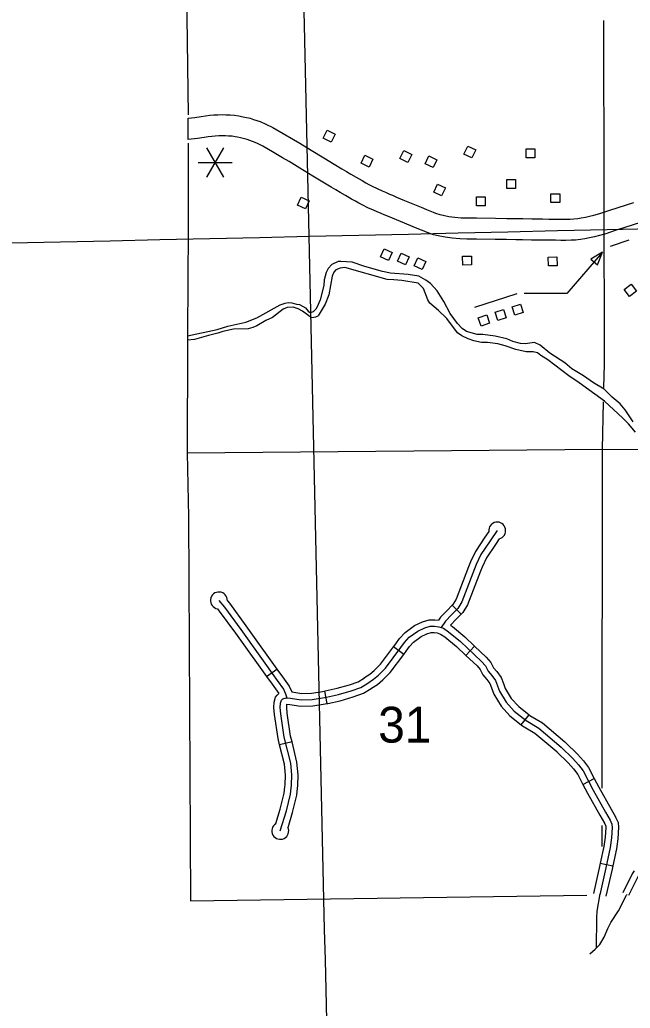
# Model space of a CAD drawing. Extents: x -19 to 366, y -4 to 359.
# Drawn here: x 127.169 to 128.531, y 197.843 to 200.051 of the extents above; entities that cross this region are included whole.
import ezdxf

# ---------------------------------------------------------------- set-up
doc = ezdxf.new("R2010")
doc.units = 0
for name, color, linetype in [('21', 7, 'Continuous'), ('R_Alt Surface', 7, 'Continuous'), ('R_Axis Annot', 7, 'Continuous'), ('R_Contour Annot', 7, 'Continuous'), ('R_ROW Annot', 7, 'Continuous'), ('R_Temp Easement', 7, 'Continuous'), ('Sheet Fence', 7, 'Continuous'), ('T_Indications', 7, 'Continuous'), ('T_Vehicle Path Lt Minor', 7, 'Continuous')]:
    doc.layers.add(name, color=color, linetype=linetype)

msp = doc.modelspace()

# ---------------------------------------------------------------- linework, layer by layer
at = {"layer": '21'}
for points in [[(127.8462, 199.7864), (127.8547, 199.8042), (127.8725, 199.7956), (127.864, 199.7779)], [(128.0174, 199.741), (128.026, 199.7588), (128.0438, 199.7502), (128.0352, 199.7325)], [(128.1602, 199.7511), (128.1687, 199.7689), (128.1865, 199.7603), (128.178, 199.7426)], [(128.2989, 199.7429), (128.2989, 199.7626), (128.3186, 199.7626), (128.3186, 199.7429)], [(127.9308, 199.7307), (127.9393, 199.7485), (127.9571, 199.7399), (127.9486, 199.7222)], [(128.0736, 199.7294), (128.0821, 199.7472), (128.0999, 199.7386), (128.0914, 199.7209)], [(128.2556, 199.6742), (128.2556, 199.694), (128.2753, 199.694), (128.2753, 199.6742)], [(128.0927, 199.6662), (128.1012, 199.6839), (128.1191, 199.6754), (128.1105, 199.6576)], [(128.3544, 199.6429), (128.3544, 199.6626), (128.3742, 199.6626), (128.3742, 199.6429)], [(127.7887, 199.6373), (127.797, 199.6552), (127.8149, 199.6469), (127.8066, 199.629)], [(128.1881, 199.6358), (128.1881, 199.6555), (128.2079, 199.6555), (128.2079, 199.6358)], [(127.9919, 199.5134), (127.974, 199.5216), (127.9822, 199.5396), (128.0001, 199.5314)], [(128.0301, 199.5038), (128.0122, 199.512), (128.0204, 199.53), (128.0383, 199.5218)], [(128.4436, 199.5167), (128.4582, 199.5041), (128.4698, 199.5324)], [(128.0671, 199.493), (128.0491, 199.5012), (128.0573, 199.5191), (128.0753, 199.511)], [(128.1773, 199.5034), (128.1576, 199.503), (128.1572, 199.5228), (128.177, 199.5231)], [(128.3683, 199.5018), (128.3486, 199.5014), (128.3482, 199.5212), (128.3679, 199.5216)], [(128.5456, 199.4446), (128.5297, 199.4329), (128.518, 199.4488), (128.5338, 199.4605)], [(128.2358, 199.3791), (128.2298, 199.3979), (128.2487, 199.4039), (128.2546, 199.3851)], [(128.2735, 199.3911), (128.2675, 199.4099), (128.2863, 199.4159), (128.2923, 199.3971)], [(128.2174, 199.3732), (128.1987, 199.3668), (128.1923, 199.3855), (128.211, 199.3919)]]:
    msp.add_lwpolyline(points, close=True, dxfattribs=at)
for points in [[(128.4872, 199.5457), (128.5293, 199.5594)], [(128.4698, 199.5324), (128.3901, 199.4397), (128.2946, 199.4397)], [(128.1847, 199.4091), (128.2787, 199.4395)]]:
    msp.add_lwpolyline(points, dxfattribs=at)
at = {"layer": 'R_Alt Surface'}
for points in [[(127.5449, 200.3115), (127.5416, 200.0569), (127.5444, 199.839)], [(127.5448, 199.7755), (127.5444, 199.5835), (127.5434, 199.3511), (127.5433, 199.3288), (127.5422, 199.084), (127.5454, 198.9405), (127.5498, 198.0835)], [(127.5498, 198.0835), (128.4346, 198.0961)]]:
    msp.add_lwpolyline(points, dxfattribs=at)
at = {"layer": 'R_Axis Annot'}
for points in [[(128.4726, 199.2294), (128.4738, 199.2814), (128.4724, 200.0492)], [(128.4695, 199.0922), (128.4719, 199.1976)], [(127.5422, 199.084), (128.4695, 199.0922)], [(128.4688, 198.3346), (128.4695, 199.0922)], [(128.4695, 199.0922), (128.5738, 199.0915)], [(128.4687, 198.2045), (128.4687, 198.2515)]]:
    msp.add_lwpolyline(points, dxfattribs=at)
at = {"layer": 'R_Contour Annot'}
for points in [[(127.5448, 199.7835), (127.5445, 199.8313), (127.5594, 199.8332), (127.5738, 199.8351), (127.5835, 199.8365), (127.5928, 199.8377), (127.6018, 199.8385), (127.6108, 199.839), (127.6203, 199.8393), (127.6291, 199.8391), (127.6383, 199.8388), (127.6482, 199.8378), (127.6576, 199.8365), (127.6639, 199.8352), (127.6711, 199.8339), (127.6828, 199.8311), (127.6907, 199.8287), (127.7055, 199.8236), (127.718, 199.8182), (127.7333, 199.8107), (127.7568, 199.7971), (127.7795, 199.7835), (127.794, 199.7752), (127.819, 199.7599), (127.8477, 199.7424), (127.8702, 199.7287), (127.888, 199.718), (127.8979, 199.712), (127.9077, 199.7065), (127.9195, 199.6996), (127.9328, 199.6918), (127.9414, 199.687), (127.9483, 199.6833), (127.9556, 199.6794), (127.9664, 199.6742), (127.9778, 199.6688), (127.9849, 199.6658), (127.9943, 199.6618), (128.0009, 199.659), (128.0099, 199.6551), (128.0278, 199.6477), (128.0459, 199.6402), (128.0649, 199.6322), (128.077, 199.6272), (128.0881, 199.6229), (128.0918, 199.6215), (128.097, 199.6194), (128.1061, 199.6164), (128.1135, 199.6145), (128.1265, 199.6119), (128.1396, 199.6101), (128.1537, 199.6089), (128.1676, 199.6085), (128.1884, 199.6084), (128.2308, 199.6077), (128.256, 199.6073), (128.2766, 199.607), (128.2917, 199.6069), (128.3117, 199.6065), (128.3253, 199.6064), (128.3355, 199.6062), (128.3494, 199.6059), (128.3651, 199.6058), (128.3764, 199.6057), (128.3869, 199.6057), (128.3976, 199.606), (128.4052, 199.6063), (128.4143, 199.6074), (128.4222, 199.6085), (128.4312, 199.6102), (128.4402, 199.6121), (128.4502, 199.6148), (128.4633, 199.6186), (128.4835, 199.6251), (128.5046, 199.6319), (128.5393, 199.6433)], [(128.554, 199.5982), (128.5192, 199.5869), (128.4981, 199.5801), (128.4771, 199.5733), (128.4629, 199.5692), (128.4514, 199.5661), (128.4405, 199.5638), (128.4299, 199.5618), (128.4205, 199.5604), (128.409, 199.5591), (128.3992, 199.5587), (128.3875, 199.5584), (128.3762, 199.5584), (128.3647, 199.5585), (128.3487, 199.5586), (128.3346, 199.5589), (128.3248, 199.559), (128.3111, 199.5591), (128.2911, 199.5595), (128.2761, 199.5597), (128.2552, 199.56), (128.2301, 199.5604), (128.1879, 199.561), (128.1669, 199.5612), (128.1511, 199.5616), (128.1343, 199.563), (128.1185, 199.5652), (128.103, 199.5683), (128.0926, 199.5709), (128.0807, 199.575), (128.0744, 199.5775), (128.0711, 199.5788), (128.0595, 199.5832), (128.0467, 199.5885), (128.0276, 199.5965), (128.0096, 199.604), (127.9915, 199.6115), (127.9824, 199.6154), (127.9758, 199.6182), (127.9662, 199.6223), (127.9584, 199.6256), (127.946, 199.6314), (127.9343, 199.6372), (127.9259, 199.6415), (127.9185, 199.6456), (127.9093, 199.6507), (127.8957, 199.6587), (127.8842, 199.6654), (127.8741, 199.6711), (127.8635, 199.6775), (127.8456, 199.6882), (127.8231, 199.7019), (127.7943, 199.7195), (127.7698, 199.7344), (127.7555, 199.7427), (127.7328, 199.7563), (127.711, 199.7689), (127.6982, 199.7752), (127.6883, 199.7794), (127.6761, 199.7837), (127.6704, 199.7854), (127.6612, 199.7876), (127.6551, 199.7887), (127.6498, 199.7897), (127.6426, 199.7908), (127.6349, 199.7915), (127.6277, 199.7918), (127.6207, 199.7919), (127.613, 199.7917), (127.6053, 199.7912), (127.5978, 199.7906), (127.5897, 199.7896), (127.5802, 199.7882), (127.5656, 199.7863), (127.5448, 199.7835)]]:
    msp.add_lwpolyline(points, dxfattribs=at)
at = {"layer": 'R_ROW Annot'}
for points in [[(128.8201, 198.5461), (128.8079, 198.5322), (128.7819, 198.5107), (128.765, 198.4923), (128.7451, 198.4693), (128.7282, 198.4417), (128.7022, 198.4065), (128.6754, 198.3666), (128.6578, 198.3398), (128.6501, 198.3153), (128.6432, 198.2823), (128.6356, 198.262), (128.621, 198.239), (128.6003, 198.2115), (128.5712, 198.1731), (128.5483, 198.1364), (128.5275, 198.0947)], [(128.54, 198.1499), (128.5359, 198.1433), (128.5148, 198.101)], [(128.4413, 197.9649), (128.453, 197.9749), (128.4632, 197.9853), (128.4732, 198.0023), (128.4814, 198.0217), (128.4882, 198.0345), (128.5054, 198.061), (128.523, 198.0955), (128.5242, 198.0976)], [(128.4558, 197.9779), (128.4565, 198.0454), (128.4578, 198.0597), (128.4645, 198.0987)]]:
    msp.add_lwpolyline(points, dxfattribs=at)
at = {"layer": 'R_Temp Easement'}
for points in [[(128.0595, 199.4787), (128.0356, 199.4824), (127.9962, 199.4852), (127.9788, 199.4887), (127.9389, 199.5002), (127.9104, 199.51), (127.8858, 199.5114), (127.8794, 199.511), (127.8651, 199.5043), (127.8573, 199.4954), (127.8526, 199.4866), (127.8483, 199.4702), (127.8474, 199.4577), (127.8392, 199.4253), (127.8326, 199.4101), (127.8293, 199.4047)], [(128.3064, 199.3091), (128.2988, 199.3093), (128.276, 199.3146), (128.2521, 199.323), (128.2361, 199.3272), (128.213, 199.3303), (128.1991, 199.3304), (128.182, 199.3343), (128.1698, 199.3387), (128.1557, 199.3453), (128.1462, 199.3519), (128.1218, 199.3841), (128.1038, 199.4017), (128.0842, 199.4184), (128.08, 199.4259), (128.0697, 199.4508), (128.0613, 199.4601), (128.0578, 199.4627), (128.0218, 199.4689), (128.0036, 199.4705), (127.9889, 199.4707), (127.8943, 199.4979), (127.8838, 199.4962), (127.8744, 199.4923), (127.8699, 199.4877), (127.8659, 199.4785), (127.8583, 199.4367), (127.8507, 199.4157), (127.8374, 199.3935), (127.8345, 199.39)], [(128.538, 199.1528), (128.5201, 199.1799), (128.5086, 199.1933), (128.491, 199.2078), (128.4729, 199.2257), (128.4496, 199.2401), (128.4274, 199.2561), (128.4011, 199.2716), (128.3854, 199.285), (128.3522, 199.3064), (128.3307, 199.3246), (128.3178, 199.3301), (128.297, 199.3271), (128.2864, 199.3284), (128.2697, 199.3327), (128.256, 199.3386), (128.2298, 199.3446), (128.2026, 199.3479), (128.1897, 199.3481), (128.1661, 199.3549), (128.1562, 199.3616), (128.1458, 199.3724), (128.1296, 199.3953), (128.1152, 199.4219), (128.1008, 199.4456), (128.0854, 199.462), (128.0755, 199.4698), (128.0595, 199.4787)], [(127.5434, 199.3455), (127.6092, 199.3592), (127.6329, 199.3668), (127.6732, 199.3754), (127.698, 199.3853), (127.7497, 199.4142), (127.761, 199.4182), (127.7681, 199.4195), (127.7761, 199.4192), (127.7863, 199.4159), (127.7931, 199.4149), (127.8065, 199.4075), (127.8123, 199.4004)], [(127.814, 199.3902), (127.8002, 199.4002), (127.7899, 199.4054), (127.7789, 199.409), (127.7656, 199.4088), (127.7566, 199.4048), (127.7331, 199.3862), (127.7177, 199.3795), (127.6979, 199.3678), (127.6889, 199.3635), (127.6787, 199.3611), (127.6462, 199.3598), (127.6221, 199.3549), (127.6108, 199.3509), (127.5901, 199.346), (127.5585, 199.3368), (127.5433, 199.3355)], [(127.8123, 199.4004), (127.8153, 199.3977), (127.8179, 199.397), (127.8242, 199.3997), (127.8293, 199.4047)], [(127.814, 199.3902), (127.8209, 199.3861), (127.8295, 199.3875), (127.8345, 199.39)], [(128.5429, 199.1302), (128.5274, 199.1485), (128.5151, 199.1612), (128.4737, 199.1992), (128.4171, 199.2403), (128.3945, 199.2559), (128.3475, 199.2919), (128.3318, 199.3011), (128.3242, 199.3071), (128.3147, 199.3096), (128.3064, 199.3091)]]:
    msp.add_lwpolyline(points, dxfattribs=at)
at = {"layer": 'Sheet Fence'}
for points in [[(132.1027, 1.3746), (131.9232, 9.99), (131.7429, 18.6056), (131.5621, 27.2214), (131.3806, 35.8373), (131.1985, 44.4533), (131.0158, 53.0695), (130.8324, 61.6859), (130.6485, 70.3024), (130.4639, 78.919), (130.2786, 87.5358), (130.0928, 96.1527), (129.9063, 104.7698), (129.7193, 113.387), (129.5316, 122.0044), (129.3433, 130.6219), (129.1543, 139.2396), (128.9648, 147.8575), (128.7746, 156.4754), (128.5838, 165.0936), (128.3925, 173.7119), (128.2005, 182.3303), (128.0078, 190.9489), (127.8146, 199.5676), (127.6208, 208.1865), (127.4264, 216.8056), (127.2313, 225.4247), (127.0357, 234.0441), (126.8394, 242.6636), (126.6425, 251.2833), (126.4451, 259.9031), (126.247, 268.523), (126.0483, 277.1431), (125.849, 285.7634), (125.6492, 294.3838), (125.4487, 303.0044), (125.2476, 311.6252), (125.0459, 320.2461), (124.8437, 328.8671), (124.6408, 337.4883), (124.4373, 346.1097)], [(0, 198.1326), (7.1014, 198.137), (14.2028, 198.1503), (21.3042, 198.1724), (28.4055, 198.2034), (35.5068, 198.2433), (42.6081, 198.292), (49.7092, 198.3496), (56.8103, 198.4161), (63.9113, 198.4913), (71.0123, 198.5755), (78.1131, 198.6685), (85.2137, 198.7704), (92.3143, 198.8811), (99.4147, 199.0007), (106.5149, 199.1291), (113.615, 199.2664), (120.7149, 199.4126), (127.8146, 199.5676), (134.9141, 199.7315), (142.0135, 199.9042), (149.1125, 200.0858), (156.2114, 200.2762), (163.31, 200.4755), (170.4084, 200.6837), (177.5065, 200.9007), (184.6043, 201.1265), (191.7018, 201.3612), (198.799, 201.6048), (205.896, 201.8572), (212.9926, 202.1185), (220.0888, 202.3886), (227.1848, 202.6676), (234.2803, 202.9554), (241.3755, 203.2521), (248.4704, 203.5576), (255.5648, 203.872), (262.6589, 204.1952), (269.7525, 204.5273), (276.8457, 204.8682), (283.9385, 205.218), (291.0309, 205.5766), (298.1228, 205.9441), (305.2142, 206.3204), (312.3051, 206.7056), (319.3956, 207.0996), (326.4856, 207.5024), (333.5751, 207.9141), (340.664, 208.3347)], [(0, 189.5162), (7.1121, 189.5206), (14.2243, 189.5339), (21.3364, 189.556), (28.4484, 189.5869), (35.5605, 189.6267), (42.6725, 189.6754), (49.7844, 189.7329), (56.8962, 189.7992), (64.0079, 189.8744), (71.1196, 189.9584), (78.2311, 190.0512), (85.3425, 190.1529), (92.4538, 190.2635), (99.5649, 190.3829), (106.6759, 190.5111), (113.7867, 190.6482), (120.8974, 190.7941), (128.0078, 190.9489), (135.1181, 191.1125), (142.2282, 191.2849), (149.338, 191.4662), (156.4476, 191.6563), (163.5569, 191.8553), (170.666, 192.0631), (177.7749, 192.2798), (184.8835, 192.5053), (191.9917, 192.7396), (199.0997, 192.9828), (206.2074, 193.2348), (213.3147, 193.4956), (220.4218, 193.7653), (227.5285, 194.0438), (234.6348, 194.3312), (241.7408, 194.6274), (248.8464, 194.9324), (255.9516, 195.2463), (263.0564, 195.569), (270.1608, 195.9005), (277.2648, 196.2409), (284.3683, 196.5901), (291.4715, 196.9481), (298.5741, 197.315), (305.6763, 197.6907), (312.7781, 198.0753), (319.8793, 198.4686), (326.9801, 198.8708), (334.0804, 199.2818), (341.1801, 199.7017)]]:
    msp.add_spline(points, degree=3, dxfattribs=at)
at = {"layer": 'T_Indications'}
for p, q in [((128.1337, 198.7432), (128.154, 198.7234)), ((128.0259, 198.6334), (128.0032, 198.6505)), ((128.1646, 198.6314), (128.1841, 198.6521)), ((127.7195, 198.5843), (127.7426, 198.6008)), ((127.8548, 198.5238), (127.85, 198.5518)), ((128.288, 198.4764), (128.3057, 198.4986)), ((127.7765, 198.4381), (127.7489, 198.4313)), ((128.4258, 198.3433), (128.451, 198.3565)), ((128.4645, 198.1674), (128.4923, 198.1614))]:
    msp.add_line(p, q, dxfattribs=at)
for points in [[(128.2344, 198.9102), (128.2187, 198.8873), (128.1983, 198.8565), (128.1875, 198.8343), (128.1557, 198.7509), (128.1467, 198.7362), (128.1328, 198.7219), (128.1188, 198.7076), (128.1091, 198.6937)], [(128.2156, 198.9079), (128.2069, 198.8953), (128.1859, 198.8636), (128.1745, 198.84), (128.1705, 198.8295)], [(128.239, 198.8918), (128.2304, 198.8794), (128.2106, 198.8495), (128.2006, 198.8287), (128.197, 198.8193)], [(128.1705, 198.8295), (128.1429, 198.7572), (128.1355, 198.745), (128.1337, 198.7432)], [(128.197, 198.8193), (128.1685, 198.7446), (128.158, 198.7275), (128.154, 198.7234)], [(127.6101, 198.7355), (127.6142, 198.7305), (127.6505, 198.6807), (127.6613, 198.6655)], [(127.6133, 198.7541), (127.6255, 198.7391), (127.662, 198.689), (127.7435, 198.5752), (127.7578, 198.5558), (127.7621, 198.5458), (127.7646, 198.5364)], [(127.6322, 198.7533), (127.6367, 198.7478), (127.6735, 198.6973), (127.6844, 198.6821)], [(128.1337, 198.7432), (128.1226, 198.7318), (128.1079, 198.7167), (128.1031, 198.7099)], [(128.154, 198.7234), (128.143, 198.712), (128.13, 198.6987)], [(127.7503, 198.2394), (127.7639, 198.2841), (127.7729, 198.3214), (127.775, 198.3414), (127.7761, 198.3643), (127.7736, 198.3908), (127.7593, 198.4484), (127.7514, 198.5007), (127.7503, 198.515), (127.7511, 198.5243), (127.7528, 198.5315), (127.7557, 198.5347), (127.7636, 198.5365), (127.7729, 198.5358), (127.7972, 198.5322), (127.8215, 198.5326), (127.8534, 198.5379), (127.8806, 198.544), (127.9088, 198.5522), (127.9299, 198.5598), (127.9457, 198.5694), (127.9586, 198.578), (127.9696, 198.5873), (127.985, 198.6027), (128.0197, 198.6489), (128.0276, 198.66), (128.0383, 198.6718), (128.0573, 198.6858), (128.0727, 198.6929), (128.0849, 198.6965), (128.0945, 198.6969), (128.1042, 198.6954), (128.1145, 198.6919), (128.126, 198.6843), (128.1528, 198.6621), (128.1997, 198.6178), (128.2083, 198.6077), (128.214, 198.5959), (128.2226, 198.5863), (128.2308, 198.5752), (128.2398, 198.5512), (128.2544, 198.5268), (128.2727, 198.5068), (128.2992, 198.4857), (128.3271, 198.4688), (128.3772, 198.4266), (128.4033, 198.4012), (128.4158, 198.3869), (128.4262, 198.3733), (128.4487, 198.3303), (128.4763, 198.2813), (128.4863, 198.263), (128.4906, 198.2544), (128.4913, 198.2473), (128.4897, 198.2235), (128.4864, 198.202), (128.4768, 198.1569), (128.4634, 198.0962)], [(128.0032, 198.6505), (128.0083, 198.6573), (128.0165, 198.6689), (128.0288, 198.6824), (128.05, 198.698), (128.0677, 198.7063), (128.0825, 198.7106), (128.0929, 198.711)], [(128.0929, 198.711), (128.0953, 198.7111), (128.1031, 198.7099)], [(128.13, 198.6987), (128.1344, 198.6958), (128.1622, 198.6728), (128.1841, 198.6521)], [(127.6844, 198.6821), (127.7426, 198.6008)], [(128.0259, 198.6334), (128.0312, 198.6405), (128.0387, 198.6511), (128.0479, 198.6612), (128.0646, 198.6735), (128.0777, 198.6796), (128.0872, 198.6824), (128.094, 198.6826)], [(128.0937, 198.6826), (128.1008, 198.6816), (128.1082, 198.679), (128.1175, 198.6729), (128.1434, 198.6515), (128.1646, 198.6314)], [(127.6613, 198.6655), (127.7195, 198.5843)], [(127.9385, 198.5817), (127.95, 198.5894), (127.96, 198.5978), (127.9743, 198.6121), (128.0032, 198.6505)], [(128.1841, 198.6521), (128.21, 198.6276), (128.2203, 198.6156), (128.2259, 198.6039), (128.2336, 198.5952), (128.2434, 198.582), (128.2483, 198.5688)], [(127.9542, 198.5581), (127.9671, 198.5666), (127.9793, 198.5768), (127.9958, 198.5934), (128.0259, 198.6334)], [(128.1646, 198.6314), (128.1894, 198.608), (128.1963, 198.5999), (128.2021, 198.588), (128.2116, 198.5773), (128.2182, 198.5683), (128.2217, 198.5589)], [(127.7195, 198.5843), (127.7321, 198.5668), (127.7471, 198.5464)], [(127.7426, 198.6008), (127.755, 198.5835), (127.7703, 198.5629), (127.7759, 198.5497)], [(127.85, 198.5518), (127.8506, 198.5519), (127.877, 198.5578), (127.9045, 198.5658), (127.9238, 198.5726), (127.938, 198.5814), (127.9385, 198.5817)], [(128.2217, 198.5589), (128.2269, 198.545), (128.243, 198.5183), (128.2629, 198.4964), (128.288, 198.4764)], [(128.2483, 198.5688), (128.2526, 198.5574), (128.2659, 198.5354), (128.2824, 198.5172), (128.3057, 198.4986)], [(127.7489, 198.4313), (127.7453, 198.4457), (127.7373, 198.4991), (127.7361, 198.515), (127.737, 198.5266), (127.7399, 198.5383), (127.7435, 198.5424)], [(127.7435, 198.5424), (127.7471, 198.5464)], [(127.7759, 198.5497), (127.7981, 198.5464), (127.8202, 198.5467), (127.85, 198.5518)], [(127.8548, 198.5238), (127.8561, 198.524), (127.8841, 198.5302), (127.9132, 198.5387), (127.9361, 198.5469), (127.9533, 198.5575), (127.9543, 198.5581)], [(127.7765, 198.4381), (127.7732, 198.4512), (127.7655, 198.5023), (127.7646, 198.515), (127.7651, 198.5221)], [(127.7651, 198.5221), (127.7713, 198.5217), (127.7963, 198.518), (127.8228, 198.5184), (127.8548, 198.5238)], [(128.3057, 198.4986), (128.3073, 198.4973), (128.3354, 198.4804), (128.3855, 198.4381)], [(128.288, 198.4764), (128.291, 198.474), (128.3188, 198.4573), (128.3672, 198.4164)], [(127.7603, 198.3377), (127.7609, 198.3425), (127.7619, 198.364), (127.7596, 198.3884), (127.7489, 198.4313)], [(127.7886, 198.3347), (127.7892, 198.3403), (127.7903, 198.3646), (127.7876, 198.3932), (127.7765, 198.4381)], [(128.3855, 198.4381), (128.3867, 198.4371), (128.4136, 198.411), (128.4268, 198.3959), (128.4382, 198.3809), (128.451, 198.3565)], [(128.3672, 198.4164), (128.3676, 198.4161), (128.393, 198.3914), (128.4048, 198.3779), (128.4141, 198.3656), (128.4258, 198.3433)], [(127.7404, 198.2555), (127.7502, 198.2879), (127.7589, 198.3238), (127.7603, 198.3377)], [(128.4258, 198.3433), (128.4362, 198.3235), (128.4638, 198.2744), (128.4737, 198.2564), (128.4739, 198.256)], [(128.451, 198.3565), (128.4612, 198.3371), (128.4887, 198.2882), (128.4989, 198.2696), (128.4993, 198.2687)], [(127.7676, 198.2472), (127.7776, 198.2804), (127.7869, 198.3189), (127.7886, 198.3347)], [(128.4739, 198.256), (128.4767, 198.2504), (128.477, 198.247), (128.4755, 198.225), (128.4725, 198.2045), (128.4645, 198.1674)], [(128.4993, 198.2687), (128.5044, 198.2584), (128.5055, 198.2475), (128.5038, 198.2219), (128.5004, 198.1994), (128.4923, 198.1614)], [(128.4645, 198.1674), (128.4629, 198.1599), (128.4495, 198.0993)], [(128.4923, 198.1614), (128.4907, 198.1538), (128.4772, 198.0932)]]:
    msp.add_lwpolyline(points, dxfattribs=at)
for centre, start, end in [((128.2344, 198.9102), 284.0967, 186.9158), ((127.6133, 198.7541), 357.5659, 260.3854), ((127.7503, 198.2394), 121.6899, 24.5093)]:
    msp.add_arc(centre, 0.0189, start, end, dxfattribs=at)
at = {"layer": 'T_Vehicle Path Lt Minor'}
for p, q in [((127.6237, 199.7652), (127.5858, 199.6996)), ((127.5858, 199.7652), (127.6237, 199.6996)), ((127.5668, 199.7324), (127.6426, 199.7324))]:
    msp.add_line(p, q, dxfattribs=at)

# ---------------------------------------------------------------- texts
at = {"layer": 'R_Axis Annot'}
msp.add_text('31', height=0.08, dxfattribs=at).set_placement((127.9688, 198.4366))

doc.saveas('drawing.dxf')
